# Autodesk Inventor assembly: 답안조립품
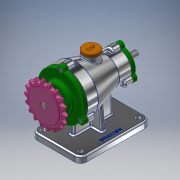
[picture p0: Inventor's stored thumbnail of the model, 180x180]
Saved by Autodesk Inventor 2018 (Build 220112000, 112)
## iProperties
Created: 2020-03
Part Number: 답안조립품
Document SubType Name: Assembly
Designer: Administrator
Author: Administrator
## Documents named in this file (15)
- C:\Users\Administrator\Desktop\700306V1009\답안조립품.iam
- C:\Users\Administrator\Desktop\700306V1009\본체.ipt
- C:\Users\Administrator\Desktop\700306V1009\앞커버.ipt
- C:\Users\Administrator\Desktop\700306V1009\뒤커버.ipt
- C:\Users\Administrator\Desktop\700306V1009\축.ipt
- C:\Users\Administrator\Desktop\700306V1009\Ű 4x4x14.ipt
- C:\Users\Administrator\Desktop\700306V1009\오일 실 17 30 8.ipt
- C:\Users\Administrator\Desktop\700306V1009\오일 실 10 20 7.ipt
- C:\Users\Administrator\Desktop\700306V1009\베어링 6203.ipt
- C:\Users\Administrator\Desktop\700306V1009\베어링 6200.ipt
- C:\Users\Administrator\Desktop\700306V1009\스프로킷.ipt
- C:\Users\Administrator\Desktop\700306V1009\개스킷 A.ipt
- C:\Users\Administrator\Desktop\700306V1009\개스킷 B.ipt
- C:\Users\Administrator\Desktop\700306V1009\마개.ipt
- C:\Users\Administrator\Desktop\700306V1009\볼트 M5.ipt
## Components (3 placed, 3 different names)
1. Ű 4x4x14:1 — 각도:2, 각도:3
2. 개스킷 A:1 — 각도:4
3. 개스킷 B:1
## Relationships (3: Angle 3)
- 각도:2 [Angle]: Ű 4x4x14:1
- 각도:3 [Angle]: Ű 4x4x14:1
- 각도:4 [Angle]: 개스킷 A:1
